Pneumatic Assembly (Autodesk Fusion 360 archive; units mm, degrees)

design "Pneumatic Assembly" references "Pivot Bracket", "Rod End", "Air Cylinder", "Pneumatic Cylinder Base Part"
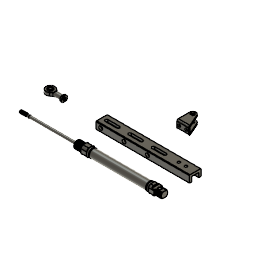
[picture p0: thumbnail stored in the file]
part number: 2025-12-15-14-01-17-457
component_insert "Component Insert1"
component_insert "Component Insert2"
component_insert "Component Insert3"
component_insert "Component Insert4"

design "Pneumatic Cylinder Base Part"
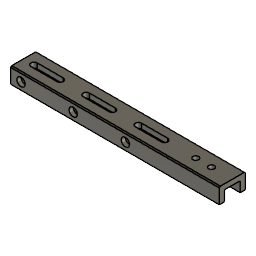
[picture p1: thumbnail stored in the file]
part number: 2025-12-15-10-30-58-806
sketch "Sketch1" plane through (0, 0, 0) normal (0, 0, 1) x axis (1, 0, 0)
  line L1 (-100, -12.5) -> (100, -12.5)
  line L2 (-100, 12.5) -> (-100, -12.5)
  line L3 (100, 12.5) -> (-100, 12.5)
  line L4 (100, -12.5) -> (100, 12.5)
  line L5 (-100, 12.5) -> (100, -12.5)
  line L6 (100, 12.5) -> (-100, -12.5)
  line L7 (0, -12.5) -> (0, 12.5)
  circle C1 centre (65, 0) radius 2.75
  circle C2 centre (80, 0) radius 2.75
  point P6 (0, 0)
  point P1 (0, 0)
  point P7 (65, 0)
  point P8 (80, 0)
  point P9 (0, 12.5)
  point P10 (0, -12.5)
  point P4 (-100, 12.5)
  point P5 (100, 12.5)
  point P3 (-100, -12.5)
  horizontal L1
  perpendicular L1 L2
  parallel L1 L3
  parallel L2 L4
  coincident L5 P6
  coincident L6 P6
  coincident P1 P6
  equal C1 C2
  horizontal P1 P7
  horizontal P6 P8
  midpoint L3 P9
  perpendicular L3 L7
  midpoint L1 P10
  dimension "d3" distance P4 P5 = 200
  dimension "d4" distance P3 P4 = 25
  dimension "d5" diameter C1 = 5.5
  dimension "d7" distance P7 P8 = 15
  dimension "d8" distance L4 P8 = 20
extrude "Extrude1" new body sketch "Sketch1" profile of L1 L2 L3 L4 C1 C2 along normal blind 5
sketch "Sketch2" plane through (100, 0, 0) normal (1, 0, 0) x axis (0, 1, 0)
  line L1 (12.5, 0) -> (-12.5, 0)
  line L2 (12.5, 5) -> (12.5, 0)
  line L3 (-12.5, 5) -> (12.5, 5)
  line L4 (-12.5, 0) -> (-12.5, 5)
  line L5 (-7.5, 0) -> (-12.5, 0)
  line L6 (-7.5, -10) -> (-7.5, 0)
  line L7 (-12.5, -10) -> (-7.5, -10)
  line L8 (-12.5, 0) -> (-12.5, -10)
  line L9 (12.5, -10) -> (12.5, 0)
  line L10 (7.5, -10) -> (12.5, -10)
  line L11 (7.5, 0) -> (7.5, -10)
  point P2 (-12.5, 0)
  point P6 (-12.5, 0)
  point P3 (12.5, 0)
  point P10 (12.5, 0)
  point P13 (7.5, 0)
  point P7 (-7.5, 0)
  point P9 (-12.5, -10)
  horizontal L5
  vertical L6
  horizontal L7
  vertical L8
  coincident P2 P6
  coincident P3 P10
  perpendicular L1 L9
  perpendicular L9 L10
  coincident L1 P13
  perpendicular L10 L11
  equal L7 L10
  collinear L7 L10
  dimension "d11" distance P6 P7 = 5
  dimension "d12" distance P6 P9 = 10
extrude "Extrude2" add sketch "Sketch2" profile of L1 L5 L6 L7 L8 L9 L10 L11 to an object
chamfer "Chamfer1" distance 1
fillet "Fillet1" radius 1
sketch "Sketch3" plane through (0, -12.5, 0) normal (0, -1, 0) x axis (1, 0, 0)
  line L1 (-100, 4) -> (100, 4)
  line L2 (-100, -10) -> (-100, 4)
  line L3 (100, -10) -> (-100, -10)
  line L4 (100, 4) -> (100, -10)
  line L5 (-90, -10) -> (-90, 4)
  point P6 (-90, 4)
  point P7 (-90, -10)
  point P8 (-90, -3)
  coincident L1 P6
  coincident L3 P7
  perpendicular L3 L5
  midpoint L5 P8
  dimension "d18" distance L2 L5 = 10
hole "Hole1" HoleDiameter 3 TipAngle 180 CBDepth 4 CBDiameter 8
work_plane "WorkPlane1" AlongDistance -10
sketch "Sketch4" plane through (-90, 0, 0) normal (-1, 0, 0) x axis (0, -1, 0)
  line L1 (-12.5, -4.5) -> (-7.5, -4.5)
  line L2 (-12.5, -10) -> (-12.5, -4.5)
  line L3 (-7.5, -10) -> (-12.5, -10)
  line L4 (8.5, -4.5) -> (8.5, -7)
  line L5 (7.5, -4.5) -> (8.5, -4.5)
  line L6 (12.5, -10) -> (7.5, -10)
  line L7 (12.5, -7) -> (12.5, -10)
  line L8 (8.5, -7) -> (12.5, -7)
  line L9 (-12.5, 4) -> (-11.5, 5)
  line L10 (-12.5, -1.5) -> (-12.5, 4)
  line L11 (-7.5, -1.5) -> (-12.5, -1.5)
  line L12 (6.5, 0) -> (-6.5, 0)
  line L13 (8.5, -1.5) -> (7.5, -1.5)
  line L14 (8.5, 1) -> (8.5, -1.5)
  line L15 (12.5, 1) -> (8.5, 1)
  line L16 (12.5, 4) -> (12.5, 1)
  line L17 (11.5, 5) -> (12.5, 4)
  line L18 (-11.5, 5) -> (11.5, 5)
  line L19 (-12.5, 4) -> (-11.5, 5)
  line L20 (-12.5, -10) -> (-12.5, 4)
  line L21 (-7.5, -10) -> (-12.5, -10)
  line L22 (-7.5, -1) -> (-7.5, -10)
  line L23 (6.5, 0) -> (-6.5, 0)
  line L24 (7.5, -10) -> (7.5, -1)
  line L25 (12.5, -10) -> (7.5, -10)
  line L26 (12.5, 4) -> (12.5, -10)
  line L27 (11.5, 5) -> (12.5, 4)
  line L28 (-11.5, 5) -> (11.5, 5)
  line L29 (-7.5, -4.5) -> (-7.5, -10)
  line L30 (7.5, -10) -> (7.5, -4.5)
  line L31 (-7.5, -1) -> (-7.5, -1.5)
  line L32 (7.5, -1.5) -> (7.5, -1)
  arc A1 centre (-6.5, -1) radius 1 clockwise from (-7.5, -1) to (-6.5, 0)
  arc A2 centre (6.5, -1) radius 1 clockwise from (6.5, 0) to (7.5, -1)
  arc A3 centre (-6.5, -1) radius 1 between (-6.5, 0) and (-7.5, -1)
  arc A4 centre (6.5, -1) radius 1 between (7.5, -1) and (6.5, 0)
sketch "Sketch5" plane through (0, 0, 5) normal (0, 0, 1) x axis (-1, 0, 0)
  line L1 (100, -11.5) -> (-100, -11.5)
  line L2 (100, 11.5) -> (100, -11.5)
  line L3 (-100, 11.5) -> (100, 11.5)
  line L4 (-100, -11.5) -> (-100, 11.5)
  line L5 (90, 0) -> (0, 0)
  line L6 (90, 0) -> (90, 12.5)
  line L7 (65, 3) -> (90, 3)
  line L8 (90, -3) -> (65, -3)
  line L9 (65, 0) -> (90, 0)
  circle C1 centre (-65, 0) radius 2.75
  circle C2 centre (-80, 0) radius 2.75
  arc A1 centre (65, 0) radius 3 clockwise from (65, -3) to (65, 3)
  arc A2 centre (90, 0) radius 3 clockwise from (90, 3) to (90, -3)
  point P1 (0, 0)
  point P9 (0, 0)
  point P8 (90, 12.5)
  point P10 (90, 12.5)
  point P17 (65, 0)
  point P11 (90, 0)
  point P16 (90, 0)
  coincident P1 P9
  perpendicular L2 L5
  coincident P8 P10
  perpendicular L1 L6
  tangent L7 A1
  tangent A1 L8
  parallel L7 L8
  tangent L8 A2
  tangent L7 A2
  coincident L5 P17
  perpendicular L6 L9
  coincident P11 P16
  dimension "d24" radius A2 = 3
  dimension "d25" distance P16 P17 = 25
extrude "Extrude3" cut sketch "Sketch5" profile of L7 A1 L8 A2 no distance stored
mirror "Mirror1" mirrorStitchTolerance 0.1
rectangular_pattern "R-Pattern1" uSpaceDistance 100 vSpaceDistance 0

design "Pivot Bracket"
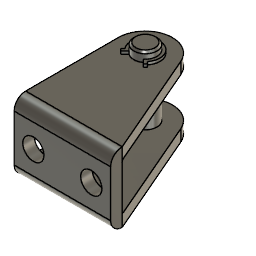
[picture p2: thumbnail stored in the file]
description: STEP AP203
part number: arrangementsContainer
base_feature "Base Feature" bodies "Clip1", "Pin", "Clip2", "Bracket"
named bodies: "Clip1", "Pin", "Clip2", "Bracket"

design "Rod End"
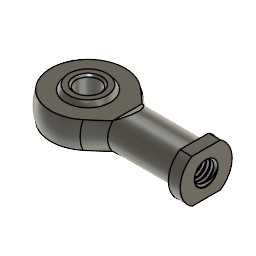
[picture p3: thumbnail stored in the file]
description: STEP AP203
part number: 6498K908_Rod End for 16mm Bore Size Double-Acting Round Body Air Cylinder
base_feature "Base Feature"

design "Air Cylinder"
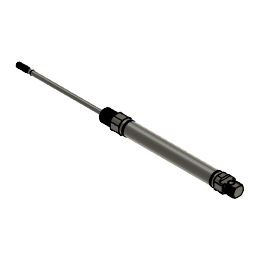
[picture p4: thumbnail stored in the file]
description: STEP AP203
part number: 6498K798_Round Body Air Cylinder
base_feature "Base Feature" bodies "Main Body", "Front Nut", "Rod", "Rear Nut"
combine "Combine1"
remove_body "RemoveBody5"
remove_body "RemoveBody6"
named bodies: "Main Body", "Front Nut", "Rod", "Rear Nut"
